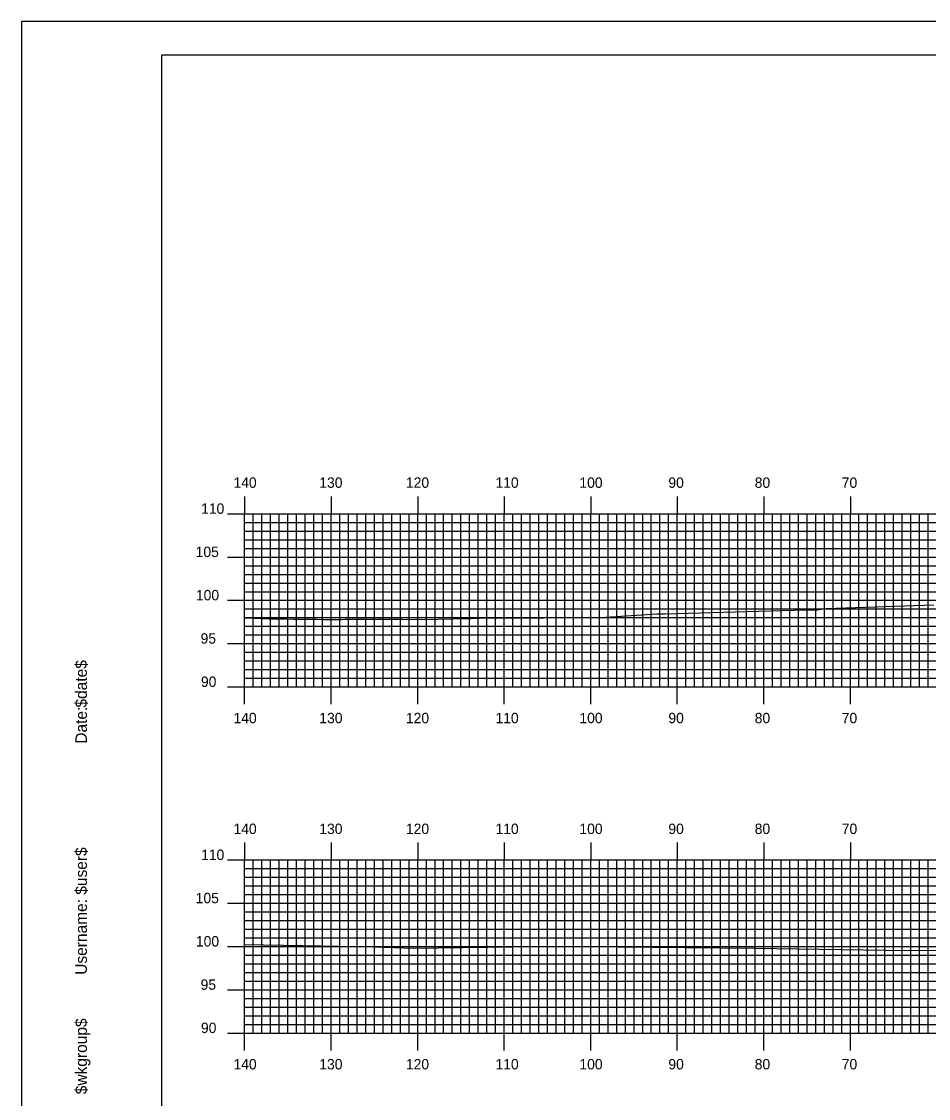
# Model space of a CAD drawing. Extents: x 1774383 to 1774727, y 442591 to 442811.
# Drawn here: x 1774383.4 to 1774488.2, y 442686.1 to 442810.5 of the extents above; entities that cross this region are included whole.
import ezdxf

# ---------------------------------------------------------------- set-up
doc = ezdxf.new("R2010")
doc.units = 0
for name, color, linetype in [('BORDER', 7, 'Continuous'), ('H_V ANNOTATION', 7, 'Continuous'), ('MAJOR', 7, 'Continuous'), ('MINOR', 7, 'Continuous'), ('PLOT BOUNDARY', 7, 'Continuous'), ('S_Roadway_Centerline', 7, 'Continuous')]:
    doc.layers.add(name, color=color, linetype=linetype)

msp = doc.modelspace()

# ---------------------------------------------------------------- linework, layer by layer
at = {"layer": 'BORDER'}
msp.add_lwpolyline([(1774399.57, 442596.67), (1774719.57, 442596.67), (1774719.57, 442806.67), (1774399.57, 442806.67)], close=True, dxfattribs=at)
at = {"layer": 'MAJOR'}
for p, q in [((1774409.17, 442755.67), (1774409.17, 442753.67)), ((1774419.17, 442755.67), (1774419.17, 442753.67)), ((1774429.17, 442755.67), (1774429.17, 442753.67)), ((1774439.17, 442755.67), (1774439.17, 442753.67)), ((1774449.17, 442755.67), (1774449.17, 442753.67)), ((1774459.17, 442755.67), (1774459.17, 442753.67)), ((1774469.17, 442755.67), (1774469.17, 442753.67)), ((1774479.17, 442755.67), (1774479.17, 442753.67)), ((1774407.17, 442753.67), (1774409.17, 442753.67)), ((1774409.17, 442753.67), (1774689.17, 442753.67)), ((1774409.17, 442733.67), (1774409.17, 442753.67)), ((1774409.17, 442733.67), (1774409.17, 442753.67)), ((1774409.17, 442753.67), (1774689.17, 442753.67)), ((1774419.17, 442733.67), (1774419.17, 442753.67)), ((1774429.17, 442733.67), (1774429.17, 442753.67)), ((1774439.17, 442733.67), (1774439.17, 442753.67)), ((1774449.17, 442733.67), (1774449.17, 442753.67)), ((1774459.17, 442733.67), (1774459.17, 442753.67)), ((1774469.17, 442733.67), (1774469.17, 442753.67)), ((1774479.17, 442733.67), (1774479.17, 442753.67)), ((1774407.17, 442748.67), (1774409.17, 442748.67)), ((1774409.17, 442748.67), (1774689.17, 442748.67)), ((1774407.17, 442743.67), (1774409.17, 442743.67)), ((1774409.17, 442743.67), (1774689.17, 442743.67)), ((1774407.17, 442738.67), (1774409.17, 442738.67)), ((1774409.17, 442738.67), (1774689.17, 442738.67)), ((1774407.17, 442733.67), (1774409.17, 442733.67)), ((1774409.17, 442733.67), (1774689.17, 442733.67)), ((1774409.17, 442733.67), (1774689.17, 442733.67)), ((1774409.17, 442731.66), (1774409.17, 442733.67)), ((1774419.17, 442731.66), (1774419.17, 442733.67)), ((1774429.17, 442731.66), (1774429.17, 442733.67)), ((1774439.17, 442731.66), (1774439.17, 442733.67)), ((1774449.17, 442731.66), (1774449.17, 442733.67)), ((1774459.17, 442731.66), (1774459.17, 442733.67)), ((1774469.17, 442731.66), (1774469.17, 442733.67)), ((1774479.17, 442731.66), (1774479.17, 442733.67)), ((1774409.17, 442715.67), (1774409.17, 442713.67)), ((1774419.17, 442715.67), (1774419.17, 442713.67)), ((1774429.17, 442715.67), (1774429.17, 442713.67)), ((1774439.17, 442715.67), (1774439.17, 442713.67)), ((1774449.17, 442715.67), (1774449.17, 442713.67)), ((1774459.17, 442715.67), (1774459.17, 442713.67)), ((1774469.17, 442715.67), (1774469.17, 442713.67)), ((1774479.17, 442715.67), (1774479.17, 442713.67)), ((1774407.17, 442713.67), (1774409.17, 442713.67)), ((1774409.17, 442713.67), (1774689.17, 442713.67)), ((1774409.17, 442693.67), (1774409.17, 442713.67)), ((1774409.17, 442693.67), (1774409.17, 442713.67)), ((1774409.17, 442713.67), (1774689.17, 442713.67)), ((1774419.17, 442693.67), (1774419.17, 442713.67)), ((1774429.17, 442693.67), (1774429.17, 442713.67)), ((1774439.17, 442693.67), (1774439.17, 442713.67)), ((1774449.17, 442693.67), (1774449.17, 442713.67)), ((1774459.17, 442693.67), (1774459.17, 442713.67)), ((1774469.17, 442693.67), (1774469.17, 442713.67)), ((1774479.17, 442693.67), (1774479.17, 442713.67)), ((1774407.17, 442708.67), (1774409.17, 442708.67)), ((1774409.17, 442708.67), (1774689.17, 442708.67)), ((1774407.17, 442703.67), (1774409.17, 442703.67)), ((1774409.17, 442703.67), (1774689.17, 442703.67)), ((1774407.17, 442698.67), (1774409.17, 442698.67)), ((1774409.17, 442698.67), (1774689.17, 442698.67)), ((1774407.17, 442693.67), (1774409.17, 442693.67)), ((1774409.17, 442693.67), (1774689.17, 442693.67)), ((1774409.17, 442693.67), (1774689.17, 442693.67)), ((1774409.17, 442691.66), (1774409.17, 442693.67)), ((1774419.17, 442691.66), (1774419.17, 442693.67)), ((1774429.17, 442691.66), (1774429.17, 442693.67)), ((1774439.17, 442691.66), (1774439.17, 442693.67)), ((1774449.17, 442691.66), (1774449.17, 442693.67)), ((1774459.17, 442691.66), (1774459.17, 442693.67)), ((1774469.17, 442691.66), (1774469.17, 442693.67)), ((1774479.17, 442691.66), (1774479.17, 442693.67))]:
    msp.add_line(p, q, dxfattribs=at)
at = {"layer": 'MINOR'}
for p, q in [((1774409.17, 442752.67), (1774689.17, 442752.67)), ((1774409.17, 442752.67), (1774411.18, 442752.67)), ((1774410.17, 442733.67), (1774410.17, 442753.67)), ((1774411.17, 442733.67), (1774411.17, 442753.67)), ((1774412.17, 442733.67), (1774412.17, 442753.67)), ((1774413.17, 442733.67), (1774413.17, 442753.67)), ((1774414.17, 442733.67), (1774414.17, 442753.67)), ((1774415.17, 442733.67), (1774415.17, 442753.67)), ((1774416.17, 442733.67), (1774416.17, 442753.67)), ((1774417.17, 442733.67), (1774417.17, 442753.67)), ((1774418.17, 442733.67), (1774418.17, 442753.67)), ((1774420.17, 442733.67), (1774420.17, 442753.67)), ((1774421.17, 442733.67), (1774421.17, 442753.67)), ((1774422.17, 442733.67), (1774422.17, 442753.67)), ((1774423.17, 442733.67), (1774423.17, 442753.67)), ((1774424.17, 442733.67), (1774424.17, 442753.67)), ((1774425.17, 442733.67), (1774425.17, 442753.67)), ((1774426.17, 442733.67), (1774426.17, 442753.67)), ((1774427.17, 442733.67), (1774427.17, 442753.67)), ((1774428.17, 442733.67), (1774428.17, 442753.67)), ((1774430.17, 442733.67), (1774430.17, 442753.67)), ((1774431.17, 442733.67), (1774431.17, 442753.67)), ((1774432.17, 442733.67), (1774432.17, 442753.67)), ((1774433.17, 442733.67), (1774433.17, 442753.67)), ((1774434.17, 442733.67), (1774434.17, 442753.67)), ((1774435.17, 442733.67), (1774435.17, 442753.67)), ((1774436.17, 442733.67), (1774436.17, 442753.67)), ((1774437.17, 442733.67), (1774437.17, 442753.67)), ((1774438.17, 442733.67), (1774438.17, 442753.67)), ((1774440.17, 442733.67), (1774440.17, 442753.67)), ((1774441.17, 442733.67), (1774441.17, 442753.67)), ((1774442.17, 442733.67), (1774442.17, 442753.67)), ((1774443.17, 442733.67), (1774443.17, 442753.67)), ((1774444.17, 442733.67), (1774444.17, 442753.67)), ((1774445.17, 442733.67), (1774445.17, 442753.67)), ((1774446.17, 442733.67), (1774446.17, 442753.67)), ((1774447.17, 442733.67), (1774447.17, 442753.67)), ((1774448.17, 442733.67), (1774448.17, 442753.67)), ((1774450.17, 442733.67), (1774450.17, 442753.67)), ((1774451.17, 442733.67), (1774451.17, 442753.67)), ((1774452.17, 442733.67), (1774452.17, 442753.67)), ((1774453.17, 442733.67), (1774453.17, 442753.67)), ((1774454.17, 442733.67), (1774454.17, 442753.67)), ((1774455.17, 442733.67), (1774455.17, 442753.67)), ((1774456.17, 442733.67), (1774456.17, 442753.67)), ((1774457.17, 442733.67), (1774457.17, 442753.67)), ((1774458.17, 442733.67), (1774458.17, 442753.67)), ((1774460.17, 442733.67), (1774460.17, 442753.67)), ((1774461.17, 442733.67), (1774461.17, 442753.67)), ((1774462.17, 442733.67), (1774462.17, 442753.67)), ((1774463.17, 442733.67), (1774463.17, 442753.67)), ((1774464.17, 442733.67), (1774464.17, 442753.67)), ((1774465.17, 442733.67), (1774465.17, 442753.67)), ((1774466.17, 442733.67), (1774466.17, 442753.67)), ((1774467.17, 442733.67), (1774467.17, 442753.67)), ((1774468.17, 442733.67), (1774468.17, 442753.67)), ((1774470.17, 442733.67), (1774470.17, 442753.67)), ((1774471.17, 442733.67), (1774471.17, 442753.67)), ((1774472.17, 442733.67), (1774472.17, 442753.67)), ((1774473.17, 442733.67), (1774473.17, 442753.67)), ((1774474.17, 442733.67), (1774474.17, 442753.67)), ((1774475.17, 442733.67), (1774475.17, 442753.67)), ((1774476.17, 442733.67), (1774476.17, 442753.67)), ((1774477.17, 442733.67), (1774477.17, 442753.67)), ((1774478.17, 442733.67), (1774478.17, 442753.67)), ((1774480.17, 442733.67), (1774480.17, 442753.67)), ((1774481.17, 442733.67), (1774481.17, 442753.67)), ((1774482.17, 442733.67), (1774482.17, 442753.67)), ((1774483.17, 442733.67), (1774483.17, 442753.67)), ((1774484.17, 442733.67), (1774484.17, 442753.67)), ((1774485.17, 442733.67), (1774485.17, 442753.67)), ((1774486.17, 442733.67), (1774486.17, 442753.67)), ((1774487.17, 442733.67), (1774487.17, 442753.67)), ((1774488.17, 442733.67), (1774488.17, 442753.67)), ((1774409.17, 442751.67), (1774689.17, 442751.67)), ((1774409.17, 442751.67), (1774411.18, 442751.67)), ((1774409.17, 442750.67), (1774689.17, 442750.67)), ((1774409.17, 442750.67), (1774411.18, 442750.67)), ((1774409.17, 442749.67), (1774689.17, 442749.67)), ((1774409.17, 442749.67), (1774411.18, 442749.67)), ((1774409.17, 442747.67), (1774689.17, 442747.67)), ((1774409.17, 442747.67), (1774411.18, 442747.67)), ((1774409.17, 442746.67), (1774689.17, 442746.67)), ((1774409.17, 442746.67), (1774411.18, 442746.67)), ((1774409.17, 442745.67), (1774689.17, 442745.67)), ((1774409.17, 442745.67), (1774411.18, 442745.67)), ((1774409.17, 442744.67), (1774689.17, 442744.67)), ((1774409.17, 442744.67), (1774411.18, 442744.67)), ((1774409.17, 442742.67), (1774689.17, 442742.67)), ((1774409.17, 442742.67), (1774411.18, 442742.67)), ((1774409.17, 442741.67), (1774689.17, 442741.67)), ((1774409.17, 442741.67), (1774411.18, 442741.67)), ((1774409.17, 442740.67), (1774689.17, 442740.67)), ((1774409.17, 442740.67), (1774411.18, 442740.67)), ((1774409.17, 442739.67), (1774689.17, 442739.67)), ((1774409.17, 442739.67), (1774411.18, 442739.67)), ((1774409.17, 442737.67), (1774689.17, 442737.67)), ((1774409.17, 442737.67), (1774411.18, 442737.67)), ((1774409.17, 442736.67), (1774689.17, 442736.67)), ((1774409.17, 442736.67), (1774411.18, 442736.67)), ((1774409.17, 442735.67), (1774689.17, 442735.67)), ((1774409.17, 442735.67), (1774411.18, 442735.67)), ((1774409.17, 442734.67), (1774689.17, 442734.67)), ((1774409.17, 442734.67), (1774411.18, 442734.67)), ((1774410.17, 442693.67), (1774410.17, 442713.67)), ((1774411.17, 442693.67), (1774411.17, 442713.67)), ((1774412.17, 442693.67), (1774412.17, 442713.67)), ((1774413.17, 442693.67), (1774413.17, 442713.67)), ((1774414.17, 442693.67), (1774414.17, 442713.67)), ((1774415.17, 442693.67), (1774415.17, 442713.67)), ((1774416.17, 442693.67), (1774416.17, 442713.67)), ((1774417.17, 442693.67), (1774417.17, 442713.67)), ((1774418.17, 442693.67), (1774418.17, 442713.67)), ((1774420.17, 442693.67), (1774420.17, 442713.67)), ((1774421.17, 442693.67), (1774421.17, 442713.67)), ((1774422.17, 442693.67), (1774422.17, 442713.67)), ((1774423.17, 442693.67), (1774423.17, 442713.67)), ((1774424.17, 442693.67), (1774424.17, 442713.67)), ((1774425.17, 442693.67), (1774425.17, 442713.67)), ((1774426.17, 442693.67), (1774426.17, 442713.67)), ((1774427.17, 442693.67), (1774427.17, 442713.67)), ((1774428.17, 442693.67), (1774428.17, 442713.67)), ((1774430.17, 442693.67), (1774430.17, 442713.67)), ((1774431.17, 442693.67), (1774431.17, 442713.67)), ((1774432.17, 442693.67), (1774432.17, 442713.67)), ((1774433.17, 442693.67), (1774433.17, 442713.67)), ((1774434.17, 442693.67), (1774434.17, 442713.67)), ((1774435.17, 442693.67), (1774435.17, 442713.67)), ((1774436.17, 442693.67), (1774436.17, 442713.67)), ((1774437.17, 442693.67), (1774437.17, 442713.67)), ((1774438.17, 442693.67), (1774438.17, 442713.67)), ((1774440.17, 442693.67), (1774440.17, 442713.67)), ((1774441.17, 442693.67), (1774441.17, 442713.67)), ((1774442.17, 442693.67), (1774442.17, 442713.67)), ((1774443.17, 442693.67), (1774443.17, 442713.67)), ((1774444.17, 442693.67), (1774444.17, 442713.67)), ((1774445.17, 442693.67), (1774445.17, 442713.67)), ((1774446.17, 442693.67), (1774446.17, 442713.67)), ((1774447.17, 442693.67), (1774447.17, 442713.67)), ((1774448.17, 442693.67), (1774448.17, 442713.67)), ((1774450.17, 442693.67), (1774450.17, 442713.67)), ((1774451.17, 442693.67), (1774451.17, 442713.67)), ((1774452.17, 442693.67), (1774452.17, 442713.67)), ((1774453.17, 442693.67), (1774453.17, 442713.67)), ((1774454.17, 442693.67), (1774454.17, 442713.67)), ((1774455.17, 442693.67), (1774455.17, 442713.67)), ((1774456.17, 442693.67), (1774456.17, 442713.67)), ((1774457.17, 442693.67), (1774457.17, 442713.67)), ((1774458.17, 442693.67), (1774458.17, 442713.67)), ((1774460.17, 442693.67), (1774460.17, 442713.67)), ((1774461.17, 442693.67), (1774461.17, 442713.67)), ((1774462.17, 442693.67), (1774462.17, 442713.67)), ((1774463.17, 442693.67), (1774463.17, 442713.67)), ((1774464.17, 442693.67), (1774464.17, 442713.67)), ((1774465.17, 442693.67), (1774465.17, 442713.67)), ((1774466.17, 442693.67), (1774466.17, 442713.67)), ((1774467.17, 442693.67), (1774467.17, 442713.67)), ((1774468.17, 442693.67), (1774468.17, 442713.67)), ((1774470.17, 442693.67), (1774470.17, 442713.67)), ((1774471.17, 442693.67), (1774471.17, 442713.67)), ((1774472.17, 442693.67), (1774472.17, 442713.67)), ((1774473.17, 442693.67), (1774473.17, 442713.67)), ((1774474.17, 442693.67), (1774474.17, 442713.67)), ((1774475.17, 442693.67), (1774475.17, 442713.67)), ((1774476.17, 442693.67), (1774476.17, 442713.67)), ((1774477.17, 442693.67), (1774477.17, 442713.67)), ((1774478.17, 442693.67), (1774478.17, 442713.67)), ((1774480.17, 442693.67), (1774480.17, 442713.67)), ((1774481.17, 442693.67), (1774481.17, 442713.67)), ((1774482.17, 442693.67), (1774482.17, 442713.67)), ((1774483.17, 442693.67), (1774483.17, 442713.67)), ((1774484.17, 442693.67), (1774484.17, 442713.67)), ((1774485.17, 442693.67), (1774485.17, 442713.67)), ((1774486.17, 442693.67), (1774486.17, 442713.67)), ((1774487.17, 442693.67), (1774487.17, 442713.67)), ((1774488.17, 442693.67), (1774488.17, 442713.67)), ((1774409.17, 442712.67), (1774689.17, 442712.67)), ((1774409.17, 442712.67), (1774411.18, 442712.67)), ((1774409.17, 442711.67), (1774689.17, 442711.67)), ((1774409.17, 442711.67), (1774411.18, 442711.67)), ((1774409.17, 442710.67), (1774689.17, 442710.67)), ((1774409.17, 442710.67), (1774411.18, 442710.67)), ((1774409.17, 442709.67), (1774689.17, 442709.67)), ((1774409.17, 442709.67), (1774411.18, 442709.67)), ((1774409.17, 442707.67), (1774689.17, 442707.67)), ((1774409.17, 442707.67), (1774411.18, 442707.67)), ((1774409.17, 442706.67), (1774689.17, 442706.67)), ((1774409.17, 442706.67), (1774411.18, 442706.67)), ((1774409.17, 442705.67), (1774689.17, 442705.67)), ((1774409.17, 442705.67), (1774411.18, 442705.67)), ((1774409.17, 442704.67), (1774689.17, 442704.67)), ((1774409.17, 442704.67), (1774411.18, 442704.67)), ((1774409.17, 442702.67), (1774689.17, 442702.67)), ((1774409.17, 442702.67), (1774411.18, 442702.67)), ((1774409.17, 442701.67), (1774689.17, 442701.67)), ((1774409.17, 442701.67), (1774411.18, 442701.67)), ((1774409.17, 442700.67), (1774689.17, 442700.67)), ((1774409.17, 442700.67), (1774411.18, 442700.67)), ((1774409.17, 442699.67), (1774689.17, 442699.67)), ((1774409.17, 442699.67), (1774411.18, 442699.67)), ((1774409.17, 442697.67), (1774689.17, 442697.67)), ((1774409.17, 442697.67), (1774411.18, 442697.67)), ((1774409.17, 442696.67), (1774689.17, 442696.67)), ((1774409.17, 442696.67), (1774411.18, 442696.67)), ((1774409.17, 442695.67), (1774689.17, 442695.67)), ((1774409.17, 442695.67), (1774411.18, 442695.67)), ((1774409.17, 442694.67), (1774689.17, 442694.67)), ((1774409.17, 442694.67), (1774411.18, 442694.67))]:
    msp.add_line(p, q, dxfattribs=at)
at = {"layer": 'PLOT BOUNDARY'}
msp.add_lwpolyline([(1774383.39, 442590.55), (1774723.39, 442590.55), (1774723.39, 442810.55), (1774383.39, 442810.55)], close=True, dxfattribs=at)
at = {"layer": 'S_Roadway_Centerline'}
for points in [[(1774409.17, 442741.64), (1774411.99, 442741.55), (1774412.58, 442741.54), (1774413.11, 442741.53), (1774413.63, 442741.53), (1774414.19, 442741.52), (1774414.79, 442741.51), (1774416.09, 442741.49), (1774416.77, 442741.48), (1774417.46, 442741.48), (1774418.14, 442741.47), (1774418.8, 442741.47), (1774419.42, 442741.46), (1774419.98, 442741.47), (1774420.37, 442741.47), (1774420.78, 442741.48), (1774421.19, 442741.48), (1774427.38, 442741.48), (1774429.64, 442741.46), (1774435.09, 442741.57), (1774435.32, 442741.58), (1774435.56, 442741.59), (1774435.81, 442741.6), (1774436.05, 442741.61), (1774436.28, 442741.62), (1774436.51, 442741.63), (1774440.08, 442741.61), (1774450.93, 442741.74), (1774456.8, 442742.11), (1774457.74, 442742.12), (1774473.99, 442742.58), (1774474.16, 442742.58), (1774474.32, 442742.59), (1774474.47, 442742.59), (1774475.34, 442742.59), (1774476.39, 442742.73), (1774488.81, 442743.15)], [(1774409.17, 442703.9), (1774415.9, 442703.79), (1774424.12, 442703.63), (1774428.66, 442703.49), (1774437.29, 442703.6), (1774442.89, 442703.69), (1774444.3, 442703.66), (1774448.37, 442703.66), (1774468.13, 442703.48), (1774485.79, 442703.22), (1774491.28, 442703.23)]]:
    msp.add_lwpolyline(points, dxfattribs=at)

# ---------------------------------------------------------------- texts
at = {"layer": 'BORDER'}
for s, p in [('$date$', (1774390.94, 442731.28)), ('Date:', (1774390.94, 442727.1)), ('$user$', (1774390.94, 442709.65)), ('Username:', (1774390.94, 442700.4)), ('$wkgroup$', (1774390.94, 442686.6))]:
    msp.add_text(s, height=1.339, rotation=90, dxfattribs=at).set_placement(p)
at = {"layer": 'H_V ANNOTATION'}
for s, p in [('140', (1774407.88, 442756.67)), ('130', (1774417.8, 442756.67)), ('120', (1774427.81, 442756.67)), ('110', (1774438.16, 442756.67)), ('100', (1774447.86, 442756.67)), ('90', (1774458.14, 442756.67)), ('80', (1774468.12, 442756.67)), ('70', (1774478.18, 442756.67)), ('110', (1774404.14, 442753.67)), ('105', (1774403.51, 442748.67)), ('100', (1774403.54, 442743.67)), ('95', (1774404.08, 442738.67)), ('90', (1774404.12, 442733.67)), ('140', (1774407.88, 442729.47)), ('130', (1774417.8, 442729.47)), ('120', (1774427.81, 442729.47)), ('110', (1774438.16, 442729.47)), ('100', (1774447.86, 442729.47)), ('90', (1774458.14, 442729.47)), ('80', (1774468.12, 442729.47)), ('70', (1774478.18, 442729.47)), ('140', (1774407.88, 442716.67)), ('130', (1774417.8, 442716.67)), ('120', (1774427.81, 442716.67)), ('110', (1774438.16, 442716.67)), ('100', (1774447.86, 442716.67)), ('90', (1774458.14, 442716.67)), ('80', (1774468.12, 442716.67)), ('70', (1774478.18, 442716.67)), ('110', (1774404.14, 442713.67)), ('105', (1774403.51, 442708.67)), ('100', (1774403.54, 442703.67)), ('95', (1774404.08, 442698.67)), ('90', (1774404.12, 442693.67)), ('140', (1774407.88, 442689.47)), ('130', (1774417.8, 442689.47)), ('120', (1774427.81, 442689.47)), ('110', (1774438.16, 442689.47)), ('100', (1774447.86, 442689.47)), ('90', (1774458.14, 442689.47)), ('80', (1774468.12, 442689.47)), ('70', (1774478.18, 442689.47))]:
    msp.add_text(s, height=1.2, dxfattribs=at).set_placement(p)
at = {"layer": 'MAJOR'}
for p in [(1774409.16, 442733.67), (1774409.16, 442693.67)]:
    msp.add_text('-', height=0.012, dxfattribs=at).set_placement(p)

doc.saveas('drawing.dxf')
